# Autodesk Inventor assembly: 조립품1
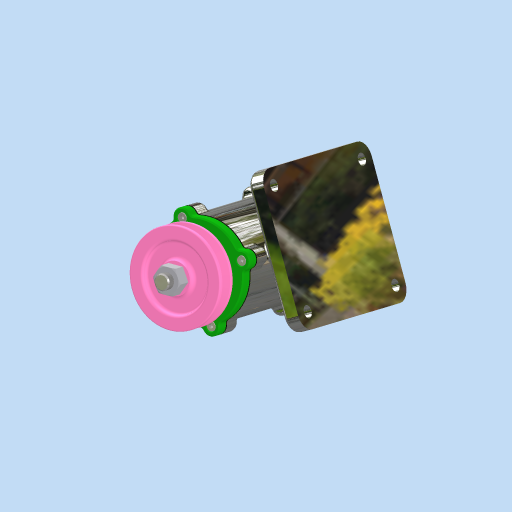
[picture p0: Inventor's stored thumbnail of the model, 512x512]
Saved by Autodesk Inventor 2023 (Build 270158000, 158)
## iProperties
Created: 2023-08
Part Number: 조립품1
Document SubType Name: Assembly
Designer: asung
Author: asung
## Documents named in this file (12)
- C:\Users\asung\Desktop\730808V1012\조립품1.iam
- C:\Users\asung\Desktop\730808V1012\본체.ipt
- C:\Users\asung\Desktop\730808V1012\베어링 6204.ipt
- C:\Users\asung\Desktop\730808V1012\개스킷.ipt
- C:\Users\asung\Desktop\730808V1012\뒤커버.ipt
- C:\Users\asung\Desktop\730808V1012\앞커버.ipt
- C:\Users\asung\Desktop\730808V1012\축.ipt
- C:\Users\asung\Desktop\730808V1012\키 4 x 4.ipt
- C:\Users\asung\Desktop\730808V1012\오일 실.ipt
- C:\Users\asung\Desktop\730808V1012\볼트 M4 x 12.ipt
- C:\Users\asung\Desktop\730808V1012\V-벨트풀리.ipt
- C:\Users\asung\Desktop\730808V1012\너트 M12 x 1.25.ipt
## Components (8 placed, 6 different names)
1. KS B 2023 6204 - 20 x 47 x 14:1
2. KS B 2023 6204 - 20 x 47 x 14:2
3. 개스킷:1
4. 개스킷:2
5. KS B 1311 (I) 4 x 4 x 12:1
6. KS B 2804 D D - 20 32 8:1
7. V-벨트풀리:1
8. KS B 1012 클래스 1 일반 - 미터 M12x1.25:1
